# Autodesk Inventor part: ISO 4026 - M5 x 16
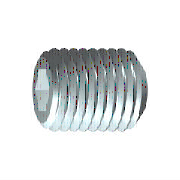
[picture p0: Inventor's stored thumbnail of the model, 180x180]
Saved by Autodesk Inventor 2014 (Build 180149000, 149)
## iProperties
Created: 2010-01
Part Number: ISO 4026 - M5 x 16
Material: Stainless Steel, 440C
Description: Hexagon socket set screws with flat point
Document SubType Name: Modeling
Standard: ISO 4026
Designer: sauflet
Standard Revision: Third edition 2003-12-01
Standards Organization: ISO
Language: en-US
Size Designation: M5 x 16
Categories: <MemberInstance><Categories><Category DisplayName="Fasteners" InternalName="e4da775c-781d-43d5-af7c-5136215cf5a6" Mnemonic="FSTN"><Category DisplayName="Bolts"
Density: 7.75 g/cm^3
Appearance: Steel
IsCustomPart: 0
Author: sauflet
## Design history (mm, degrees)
sketch "Sketch1"
  geometry: L1 (0, 0)-(12.167, 0); L2 (16, 1.443)-(16, 2.5); L3 (16, 2.5)-(0, 2.5); L4 (16, 1.443)-(13, 1.443); L5 (13, 1.443)-(12.167, 0); L6 (0, -0.5)-(0, 3) reference; L7 (0, 2.5)-(0, 0)
  constraints: 13 end point, 3 parallel, 1 collinear, 1 perpendicular, 1 point on line
  dimensions: "d0" = 3 distance of L2.start L4.end (= INTI); "d1" = 60 deg angle of L5 L1; "d2" = 5 diameter of L3 L1 (= NND); "d3" = 2.88675 diameter of L4 L1 (= 1.1547 x SW); "d5" = 16 distance from line of L2 L3.end (= NLG)
revolve "Body" sketch "Sketch1" stored, may be unused: angle "d6" = 90 deg
sketch "Sketch2"
  geometry: L1 (-0.722, 1.25)-(0.722, 1.25); L2 (0.722, 1.25)-(1.443, 0); L3 (1.443, 0)-(0.722, -1.25); L4 (0.722, -1.25)-(-0.722, -1.25); L5 (-0.722, -1.25)-(-1.443, 0); L6 (-1.443, 0)-(-0.722, 1.25); A1 r 1.443 centre (0, 0) between (-0.722, 1.25) and (0.722, 1.25) reference; 2 further points
  constraints: 12 end point, 2 point on circle, 1 coincident, 1 horizontal, 11 other
extrude "Slot" join sketch "Sketch2" taper "d9" = 0 deg; stored distance "d21" = 10
workaxis "Work Axis1"
workplane "Work Plane1"
body "Solid1"
chamfer "Chamfer1" distance "d7" = 0.49076 (= -0.5 x GD1 + 0.5 x NND); stored, may be unused: angle "d8" = 45 deg (= FAWI), second distance "d29" = 0.49076 (= -0.5 x GD1 + 0.5 x NND)
feature "Thread" dims "d11" = 16 (= NLG), "d12" = 0
chamfer "Chamfer2" distance "d13" = 0.49076 (= -0.5 x GD1 + 0.5 x NND); stored, may be unused: angle "d14" = 45 deg (= FAWI), second distance "d30" = 0.49076 (= -0.5 x GD1 + 0.5 x NND)
other parameters: "NND" = 5 [user parameter; used in 5 equation terms], "NLG" = 16 [user parameter; used in 2 equation terms], "INTI" = 3 [user parameter; used in 1 equation term], "FAWI" = 45 deg [user parameter; used in 2 equation terms], "SW" = 2.5 [user parameter; used in 2 equation terms], "GD1" = 4.01848 (= THREADDIA - 1.2269 x PTC) [user parameter; used in 4 equation terms], "d4" = 0, "FAWI1" = 45 deg [user parameter], "d15" = 0, "d31" = 0, "GUL" = 0.49076 (= 0.61345 x PTC) [user parameter], "SPD" = 3.5 [user parameter], "SEWI" = 90 deg [user parameter], "TOA" = 30 deg [user parameter], "THREADDIA" = 5 [user parameter; used in 1 equation term], "TPU" = 12.5 (computed from PTC) [user parameter], "PTC" = 0.8 [user parameter; used in 4 equation terms], "GAL" = 0.49076 (= 0.61345 x PTC) [user parameter], "E0" = 2.8875 (= 1.155 x SW) [user parameter]
